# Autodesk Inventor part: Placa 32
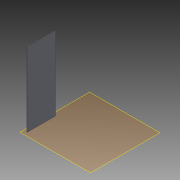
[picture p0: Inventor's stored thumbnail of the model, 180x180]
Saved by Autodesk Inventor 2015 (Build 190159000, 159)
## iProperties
Created: 2015-04
Part Number: Placa 32
Material: Generic
Document SubType Name: Modeling
Designer: suporte
Density: 1 g/cm^3
Appearance: Default
Author: suporte
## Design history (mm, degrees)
workplane "Work Plane1"
sketch "Sketch1"
  geometry: L1 (-787.5, -887.5)-(-912.5, -887.5) reference; L2 (-912.5, -887.5)-(-900, -887.5); L3 (-900, -887.5)-(-900, -87.5); L4 (-900, -87.5)-(-912.5, -87.5); L5 (-912.5, -87.5)-(-912.5, -887.5); 1 further point
  constraints: 8 end point, 2 parallel, 1 horizontal, 1 perpendicular
  dimensions: "d0" = 12.5 distance of L4.end L3.end; "d1" = 800 distance of L3.end L2.end
extrude "Extrusion1" new body sketch "Sketch1" distance "d2" = 2100; taper "d3" = 0 deg
body "Solid1"
node "Reference1"
